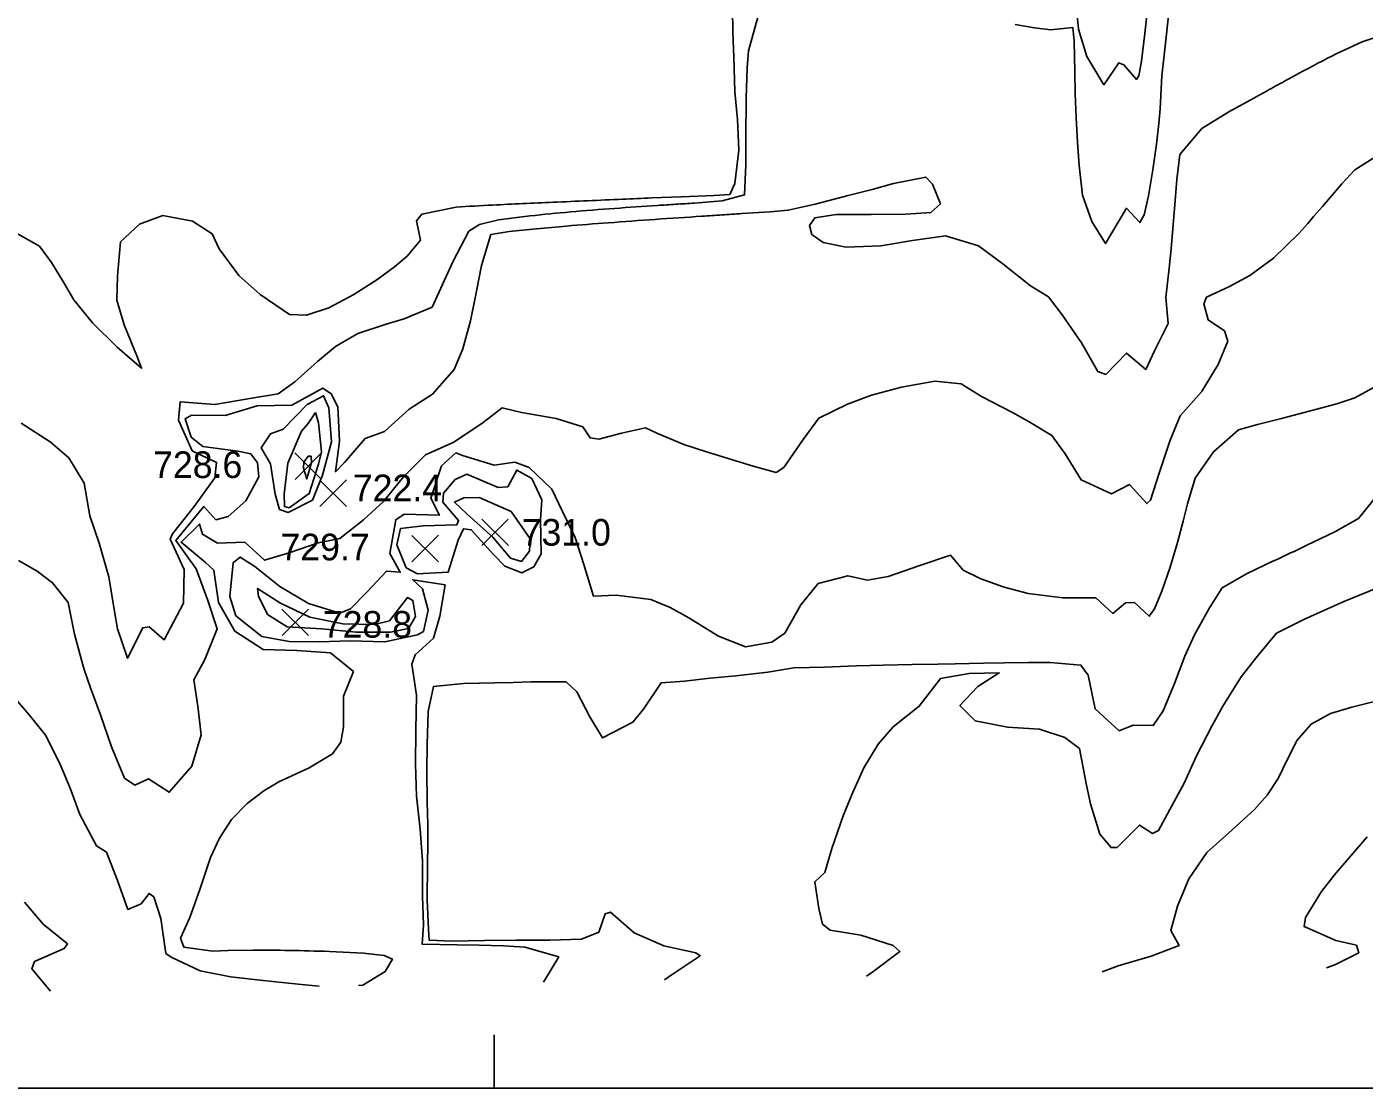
# Model space of a CAD drawing. Extents: x 2566079 to 2571326, y 424054 to 426896.
# Drawn here: x 2568737 to 2569490, y 424077 to 424675 of the extents above; entities that cross this region are included whole.
import ezdxf

# ---------------------------------------------------------------- set-up
doc = ezdxf.new("R2010")
doc.units = 0
for name, color, linetype in [('Contour_ADS_Major', 7, 'Continuous'), ('Contour_ADS_Minor', 7, 'Continuous'), ('Contour_ADS_Spot_Elevation', 7, 'Continuous'), ('Contour_ADS_State_Plane_Border', 7, 'Continuous')]:
    doc.layers.add(name, color=color, linetype=linetype)

# ---------------------------------------------------------------- blocks, each defined once
blk = doc.blocks.new('S750')
at = {"layer": 'Contour_ADS_Spot_Elevation'}
for p, q in [((-0.5, 0.498), (0.5, -0.498)), ((-0.498, -0.5), (0.498, 0.5))]:
    blk.add_line(p, q, dxfattribs=at)

msp = doc.modelspace()

# ---------------------------------------------------------------- linework, layer by layer
at = {"layer": 'Contour_ADS_Major'}
for points in [[(2569148.4, 424680.26), (2569143.26, 424661.28), (2569142.39, 424651.69), (2569141.92, 424634.68)], [(2569379.5, 424681), (2569377.6, 424663.89), (2569375.78, 424647.26), (2569374.83, 424628.73), (2569374.11, 424620.32), (2569372.8, 424608.77), (2569370.8, 424594.24), (2569368.36, 424579.73), (2569365.83, 424568.96), (2569363.52, 424564.6), (2569355.9, 424572.66), (2569347.6, 424558.77), (2569344.15, 424552.78), (2569336.49, 424565.18), (2569331.23, 424580.05), (2569329.37, 424596.73), (2569328.41, 424609.75), (2569327.61, 424623.78), (2569327.12, 424637.23), (2569326.84, 424649.29), (2569326.4, 424666.86), (2569325.64, 424674.5), (2569313.31, 424673.2), (2569304.06, 424674.2), (2569293.31, 424676.06)], [(2569141.74, 424614.53), (2569141.65, 424597.04), (2569140.95, 424580.15), (2569128.29, 424576.79), (2569112.83, 424575.6)], [(2569020.24, 424568.38), (2569002.52, 424566.06), (2568991.77, 424563.55), (2568985.88, 424559.68), (2568976.96, 424542.97), (2568971.94, 424531.73), (2568965.18, 424516.99), (2568949.39, 424510.41), (2568939.36, 424507.46), (2568923.33, 424502.22), (2568910.71, 424494.91), (2568900.61, 424486.41), (2568887.81, 424474.87), (2568878.51, 424468.21), (2568862.59, 424465.54), (2568842.96, 424462.07), (2568823.37, 424463.74), (2568822.37, 424453.26), (2568830.2, 424436.13), (2568843.86, 424429.43), (2568842.85, 424420.84), (2568831.24, 424404.73), (2568819.03, 424389.35), (2568817.81, 424386.3), (2568825.65, 424369.25), (2568825.19, 424350.35), (2568817.96, 424336.48), (2568814.45, 424329.64), (2568805.9, 424336.89), (2568802.3, 424336.46), (2568793.65, 424319.25), (2568788.19, 424335.89), (2568786.44, 424345.58), (2568783.28, 424365.11), (2568777.73, 424384.13), (2568772.56, 424399.48), (2568769.25, 424417.78), (2568760.78, 424432.06), (2568750.24, 424441.21), (2568733.97, 424451.64)], [(2569501.39, 424360.56), (2569487.05, 424354.87), (2569477.9, 424351.07), (2569466.89, 424346.21), (2569455.66, 424341.03), (2569440.33, 424333.31), (2569429.44, 424320.17), (2569420.47, 424308.85), (2569410.19, 424292.35), (2569404, 424280.98), (2569395.34, 424264.39), (2569388.4, 424248.97), (2569380.4, 424234.15), (2569374, 424222.23), (2569370.57, 424220.62), (2569363.2, 424225.3), (2569350.74, 424212.78), (2569347.23, 424212.68), (2569340.83, 424220.23), (2569335.66, 424237.31), (2569333.27, 424248.8), (2569329.46, 424268.4), (2569321.13, 424274.65), (2569306.99, 424279.24), (2569289.01, 424280.5), (2569270.79, 424284.02), (2569262.18, 424292.68), (2569272.27, 424303.38), (2569284.32, 424311.02), (2569267.34, 424310.71), (2569251.23, 424307.8), (2569239.28, 424292.19), (2569224.64, 424280.59), (2569216.08, 424270.97), (2569208.17, 424257.51), (2569201.49, 424242.85), (2569196.53, 424230.47), (2569190.12, 424212.21), (2569186.07, 424198.63), (2569180.58, 424193.37), (2569182.69, 424178.35), (2569184.87, 424169.61), (2569189.07, 424166.21), (2569206.45, 424163.34), (2569224.68, 424157.44), (2569228.45, 424154.08), (2569213.2, 424142.67), (2569209.59, 424140.18)]]:
    msp.add_lwpolyline(points, dxfattribs=at)
msp.add_lwpolyline([(2568984.81, 424400.49), (2568999.4, 424387.44), (2569009.21, 424375.7), (2569015.54, 424373.75), (2569020.04, 424379.57), (2569020.37, 424386.53), (2569009.57, 424401.86), (2568991.66, 424409.74), (2568983.04, 424409.66), (2568977.73, 424407.1), (2568984.81, 424400.49)], close=True, dxfattribs=at)
for centre, radius, start, end in [((2572181.95, 424597.45), 3040.26, 179.29831, 179.67807), ((2569195.24, 422826.96), 1750.28, 94.17446, 94.98989), ((2569403.65, 419848.15), 4736.36, 93.77388, 94.06586), ((2569573.33, 417249.65), 7340.39, 93.678631, 93.76045), ((2569001.81, 426202.51), 1630.69, 273.53539, 273.90369), ((2569128.54, 423575.81), 998.46, 94.91484, 96.22713)]:
    msp.add_arc(centre, radius, start, end, dxfattribs=at)
at = {"layer": 'Contour_ADS_Minor'}
for points in [[(2569134.16, 424685.01), (2569134.46, 424671.9), (2569134.91, 424657.69), (2569135.48, 424638.16), (2569136.95, 424622.74), (2569137.82, 424605.39), (2569135.5, 424586.56), (2569132.71, 424580.47), (2569123.92, 424579.94), (2569105.33, 424579.15), (2569088.82, 424578.45)], [(2569368.25, 424690.31), (2569366.25, 424671.12), (2569364.4, 424655.45), (2569362.9, 424647.22), (2569361.47, 424645.24), (2569354.44, 424653.44), (2569351.53, 424654.49), (2569343.17, 424642.25), (2569333.51, 424658.22), (2569328.88, 424673.45), (2569327.82, 424685.09)], [(2569502.06, 424670.91), (2569488.49, 424666.36)], [(2569427.66, 424634.74), (2569413.53, 424626.97), (2569398.33, 424617.63), (2569385.92, 424602.88), (2569384.26, 424588.83), (2569382.89, 424572.41), (2569382.07, 424561.36), (2569381.09, 424549.85), (2569379.92, 424538.99), (2569377.99, 424522.47), (2569379.32, 424507.7), (2569371.59, 424492.32), (2569366.8, 424481.78), (2569355.83, 424491.11), (2569344.3, 424479.08), (2569339.74, 424480.81), (2569330.51, 424496.86), (2569319.81, 424512.63), (2569311.99, 424522.73), (2569301.96, 424528.99), (2569286.27, 424541.29), (2569272.61, 424551.45), (2569254.01, 424557.05), (2569235.49, 424554.49), (2569217.68, 424551.6), (2569198.25, 424550.8), (2569185.28, 424553.34), (2569178.93, 424557.94), (2569177.46, 424563.01), (2569180.52, 424567.27), (2569192.56, 424569.22), (2569212.21, 424569.25), (2569231.66, 424569.32), (2569245.83, 424570.25), (2569251.18, 424575.18), (2569246.84, 424586.16), (2569242.92, 424590.23), (2569224.88, 424586.64), (2569212.76, 424583.24), (2569199.35, 424579.92), (2569180.63, 424574.93), (2569165.61, 424571.57), (2569155.43, 424570.74), (2569139.52, 424569.66)], [(2569498.08, 424603), (2569484.43, 424594.29), (2569477.09, 424586.48), (2569466.17, 424573.68)], [(2568978.68, 424573.33), (2568959.31, 424569.29), (2568956.42, 424565.64), (2568958.7, 424554.74), (2568951.06, 424545.73), (2568944.05, 424539.74), (2568934.05, 424532.34), (2568921.1, 424524.04), (2568907.1, 424516.69), (2568894.39, 424512.45), (2568884.82, 424512.75), (2568868.44, 424524.2), (2568856.29, 424534.82), (2568845.22, 424549.86), (2568841.35, 424558.2), (2568830.36, 424565.33), (2568813.59, 424568.63), (2568800.43, 424563.8), (2568789.73, 424553.69), (2568788.06, 424534.64), (2568787.72, 424520.95), (2568791.85, 424507.1), (2568799.34, 424488.63), (2568801.68, 424482.57), (2568788, 424494.52), (2568774.08, 424508.1), (2568763.45, 424521.19), (2568757.72, 424531.05), (2568750.96, 424542.19), (2568744.23, 424551.31), (2568729.27, 424559.69)], [(2569040.78, 424562.63), (2569021.91, 424560.97), (2569008.58, 424559.64), (2568998.22, 424557.84), (2568992.9, 424540.38), (2568990.18, 424526.02), (2568986.7, 424509.19), (2568982.46, 424493.54), (2568977.48, 424481.91), (2568965.41, 424467.99), (2568952.17, 424459.56), (2568938.29, 424446.92), (2568927.43, 424442.97), (2568915.87, 424429.41), (2568910.77, 424424.31), (2568912.96, 424441.54), (2568912.08, 424460.87), (2568908.39, 424468.21), (2568903.66, 424471.38), (2568886.16, 424461.73), (2568866.71, 424461.49), (2568848.75, 424455.94), (2568829.82, 424456.2), (2568826.17, 424454.12), (2568829.58, 424443.73), (2568836.05, 424438.58), (2568855.73, 424435.97), (2568863.04, 424434.41), (2568866.88, 424429.3), (2568867.61, 424421.37), (2568860.24, 424407.84), (2568850.3, 424399.04), (2568843.44, 424397.22), (2568836.69, 424404.68), (2568824.36, 424389.76), (2568821.01, 424385.65), (2568832.44, 424369.64), (2568838.93, 424351.8), (2568844.12, 424335.84), (2568837.22, 424318.61), (2568831.1, 424307.1), (2568833.36, 424292.33), (2568835.22, 424276.12), (2568829.95, 424258.55), (2568817.26, 424243.85), (2568805.49, 424251.42), (2568797.79, 424247.72), (2568792.09, 424251.79), (2568784.7, 424269.42), (2568778.5, 424287.31), (2568772.85, 424302.67), (2568769.1, 424313.47), (2568763.91, 424332.77), (2568760.39, 424350.61), (2568751.61, 424361.76), (2568742.83, 424368.33), (2568732.46, 424374.33)], [(2569452.84, 424558.54), (2569438.71, 424544.65), (2569425.31, 424534.79), (2569413.87, 424528.59), (2569400.96, 424522.55), (2569399.39, 424518.92), (2569401.85, 424509.81), (2569411.08, 424503.61), (2569412.89, 424497.87), (2569407.49, 424484.64), (2569398.2, 424469.34), (2569386.14, 424455.71), (2569380.53, 424442.03), (2569374.34, 424423.53), (2569369.44, 424408.21), (2569367.45, 424406.39), (2569357.59, 424417.04), (2569347.4, 424411.88), (2569330.33, 424419.7), (2569321.44, 424434.36), (2569313.9, 424444.71), (2569301.09, 424452.45), (2569291.7, 424457.64), (2569274.36, 424466.71), (2569262.95, 424473.79), (2569248.13, 424475.36), (2569229.25, 424471.86), (2569212.42, 424467.45), (2569198.89, 424462.34), (2569182.69, 424454.38), (2569173.91, 424442.36), (2569163.1, 424426.76), (2569158.78, 424423.92), (2569145.76, 424427.38), (2569133.63, 424431.25), (2569119.59, 424435.51), (2569106.77, 424439.66), (2569091.7, 424446.07), (2569085.18, 424448.93), (2569071.82, 424446), (2569059.05, 424442.64), (2569054.08, 424443.38), (2569049.89, 424449.56), (2569035.05, 424454.24), (2569015.37, 424457.69), (2569004.65, 424460.32), (2568993.93, 424452.08), (2568977.36, 424440.95), (2568961.35, 424433.87), (2568948.97, 424421.39), (2568937.85, 424407.54), (2568926.55, 424397.17), (2568913.28, 424386.74), (2568901.11, 424384.26), (2568884.62, 424378.69), (2568870.84, 424374.49), (2568859.7, 424384.65), (2568844.4, 424384.14), (2568835.97, 424389.06), (2568834.16, 424394.84), (2568823.89, 424384.61), (2568837.66, 424373.1), (2568842.34, 424368.84), (2568845, 424350.64), (2568854.1, 424334.49), (2568870.01, 424324.27), (2568889.09, 424323.54), (2568908.01, 424322.32), (2568920.82, 424311.75), (2568915.35, 424297.91), (2568915.35, 424280.7), (2568913.7, 424272.02), (2568909.05, 424265.39), (2568895.91, 424257.53), (2568878.81, 424249.74), (2568870.41, 424244.54), (2568861.05, 424237.39), (2568852.32, 424228.42), (2568845.47, 424217.98), (2568840.45, 424207.13), (2568834.39, 424189.04), (2568828.78, 424173.21), (2568823.57, 424161.61), (2568825.35, 424156.59), (2568841.83, 424154.38), (2568850.37, 424154.72), (2568864.37, 424154.9)], [(2569496.46, 424472.44), (2569484.39, 424465.86), (2569474.34, 424462.61), (2569459.51, 424458.53), (2569443.18, 424454.3), (2569429.63, 424450.86), (2569419.02, 424447.86), (2569404.86, 424435.47), (2569394.6, 424420.63), (2569390.19, 424406.24), (2569387.8, 424396.49), (2569384.65, 424384.54), (2569380.46, 424370.57), (2569375.87, 424357.09), (2569371.74, 424347.14), (2569368.71, 424342.92), (2569360.48, 424350.75), (2569355.4, 424350.53), (2569348.21, 424344.47), (2569338.63, 424353.28), (2569320.08, 424353.38), (2569300.62, 424355.78), (2569287.17, 424359.37), (2569273.95, 424364.06), (2569264.07, 424368.9), (2569256.81, 424377.26), (2569239.57, 424371.58), (2569221.81, 424365.39), (2569210.26, 424363.24), (2569199.12, 424365.61), (2569182.4, 424361.41), (2569172.69, 424349.41), (2569163.74, 424333.44), (2569156.3, 424328.25), (2569141.45, 424325.71), (2569126.28, 424331.66), (2569109.62, 424342.03), (2569099.13, 424347.84), (2569088.24, 424352.31), (2569068.74, 424354.88), (2569055.95, 424354.27), (2569050.57, 424372.06), (2569045.74, 424387.31), (2569038.45, 424401.97), (2569032.58, 424414.51), (2569019.69, 424426.7), (2569011.7, 424429.68), (2569000.14, 424427.96), (2568982.28, 424433.42), (2568978.59, 424434.86), (2568970.51, 424427.69), (2568964.38, 424409.39), (2568969.3, 424399.84), (2568949.51, 424400.39), (2568944.7, 424397.25), (2568941.34, 424378.23), (2568947.25, 424367.72), (2568939.48, 424368.27), (2568928.57, 424356.63), (2568919.29, 424347.18), (2568913.16, 424344.65), (2568895.61, 424350.13), (2568879.49, 424359.68), (2568865.3, 424371), (2568857.17, 424376.21), (2568853.17, 424373.05), (2568851.38, 424354.13), (2568854.67, 424343.24), (2568869.25, 424331.51), (2568884.74, 424328.74), (2568901.58, 424328.42), (2568919.11, 424329.07), (2568938.5, 424328.51), (2568956.9, 424332.44), (2568960.33, 424334.42), (2568962.92, 424346.34), (2568959.71, 424358.29), (2568954.28, 424363.45), (2568972.49, 424360.52), (2568969.55, 424342.95), (2568965.94, 424330.62), (2568955.66, 424321.2), (2568953.69, 424315.9), (2568956.33, 424298.47), (2568956.03, 424278.82), (2568955.86, 424259.55), (2568956.41, 424241.57), (2568958.34, 424223.02), (2568959.67, 424205.27)], [(2569617.85, 424456.24), (2569605.01, 424453.48), (2569586.25, 424449.5), (2569571.48, 424444.86), (2569559.82, 424438.14), (2569543.01, 424430.38), (2569528.5, 424428), (2569516.06, 424422.36), (2569502.02, 424411.97), (2569496.79, 424410.64), (2569486.43, 424397.99), (2569473.22, 424390.53), (2569457.46, 424382.89)], [(2569439.09, 424374.22), (2569423.38, 424366.83), (2569409.68, 424358.97), (2569402.6, 424347.59), (2569394.15, 424332.38), (2569388.74, 424320.35), (2569382.92, 424304.98), (2569376.53, 424289.59), (2569370.95, 424281.32), (2569359.62, 424281.67), (2569351.78, 424278.48), (2569338.23, 424290.72), (2569334.42, 424309.76), (2569330.26, 424315.43), (2569312.94, 424316.92), (2569300.78, 424316.83), (2569287.28, 424316.63), (2569275.37, 424316.42), (2569259.47, 424316.13), (2569249.72, 424315.98), (2569235.39, 424315.74), (2569218.92, 424315.43), (2569203.92, 424315.04), (2569186.06, 424314.23), (2569168.69, 424313.92), (2569154.07, 424311.36), (2569136.08, 424309.34), (2569121.62, 424308.11), (2569107.13, 424306.42), (2569093.96, 424305.39), (2569084.02, 424290.64), (2569078.13, 424283.21), (2569061.09, 424274.45), (2569053.98, 424286.36), (2569046.59, 424300.3), (2569040.55, 424305.9), (2569020.67, 424306.01), (2569010.79, 424305.7), (2569000.44, 424305.47), (2568982.72, 424305.06), (2568965.85, 424303.35), (2568963.02, 424289.33), (2568962.46, 424270.76), (2568962.22, 424255.78), (2568962.35, 424238.34), (2568962.71, 424225.6), (2568962.7, 424214.78), (2568962.58, 424202.86), (2568962.36, 424183.34), (2568963.15, 424166.47), (2568963.58, 424160.46), (2568976.26, 424159.87), (2568994.62, 424160.37), (2569012.58, 424160.51), (2569031.39, 424160.59), (2569049.16, 424160.99), (2569058.99, 424165.08), (2569062.51, 424175.36), (2569065.63, 424176.33), (2569078.85, 424164.64), (2569095.46, 424157.3), (2569113.65, 424153.34), (2569116.02, 424151.69), (2569099.77, 424140.72), (2569095.95, 424138.11)], [(2568901.64, 424134.58), (2568891.69, 424135.54), (2568880.74, 424136.69), (2568870.01, 424137.81), (2568851.76, 424139.79), (2568834.63, 424143.15), (2568818.3, 424150.9), (2568815.25, 424153.09), (2568812.47, 424172.72), (2568808.52, 424184.85), (2568805.83, 424186.86), (2568801.39, 424181), (2568793.98, 424177.82), (2568788.12, 424194.12), (2568781.86, 424210.1), (2568776.2, 424213.58), (2568766.96, 424231.28), (2568761.38, 424246.15), (2568756.07, 424259.03), (2568747.83, 424275.82), (2568738.35, 424287.36), (2568728.28, 424299.26)], [(2569500.77, 424296.26), (2569482.67, 424291.78), (2569470.73, 424288.17), (2569459.78, 424282.08), (2569452.03, 424273.06), (2569446.47, 424262.36), (2569441.29, 424251.63), (2569435.06, 424242.2), (2569427.95, 424234.11), (2569413.34, 424220.75), (2569401.22, 424209.8), (2569390.91, 424195.07), (2569384.61, 424179.69), (2569380.93, 424166.02), (2569385.49, 424157.42), (2569369.84, 424151.57), (2569351.29, 424145.98), (2569342.27, 424142.59)], [(2569491.35, 424218.61), (2569482.09, 424208.09), (2569473.06, 424197.34), (2569465.65, 424187.97), (2569456.73, 424173.27), (2569455.83, 424168.12), (2569473.82, 424160.4), (2569485.31, 424157.67), (2569486.58, 424153.41), (2569473.15, 424146.57), (2569468.42, 424144.89)], [(2568959.67, 424205.27), (2568959.83, 424185.38), (2568960.29, 424169.07), (2568959.63, 424158.19), (2568979.18, 424157.84), (2568991.63, 424157.76), (2569005.24, 424157.4), (2569017.32, 424156.59), (2569036.37, 424151.07), (2569027.83, 424136.87)], [(2568750.48, 424131.83), (2568739.9, 424144.29), (2568741.33, 424148.43), (2568758.09, 424155.79), (2568760.03, 424158.36), (2568746.2, 424169.44), (2568735.8, 424182)], [(2568907.32, 424154.13), (2568926.55, 424153.19), (2568938.16, 424151.87), (2568942.82, 424149.89), (2568938.79, 424142.82), (2568926.09, 424135.23), (2568923.64, 424134.98)]]:
    msp.add_lwpolyline(points, dxfattribs=at)
for points in [[(2568894.82, 424462.23), (2568881.39, 424448.26), (2568874.13, 424445.59), (2568869.02, 424437.71), (2568874.17, 424428.69), (2568876.89, 424411.73), (2568879.23, 424403.11), (2568884.21, 424401.28), (2568897.82, 424408.23), (2568903.53, 424422.32), (2568908.48, 424441.16), (2568907.09, 424460.37), (2568904.06, 424467.1), (2568894.82, 424462.23)], [(2568899.45, 424457.58), (2568895.48, 424451.44), (2568891.67, 424447.17), (2568883.94, 424429.15), (2568881.8, 424411.64), (2568882.03, 424404.72), (2568884.77, 424403.9), (2568895.9, 424412.04), (2568901.18, 424428.55), (2568902.95, 424435.5), (2568901.12, 424451.87), (2568899.45, 424457.58)], [(2568892.8, 424426.38), (2568894.64, 424420.27), (2568897.36, 424429.59), (2568897.05, 424433.05), (2568895.47, 424433.12), (2568892.87, 424429.6), (2568892.8, 424426.38)], [(2568950.49, 424370.23), (2568956.98, 424366.83), (2568974.27, 424367.74), (2568979.78, 424385.83), (2568982.77, 424392.22), (2568987.22, 424391.63), (2568999.95, 424377.54), (2569006.08, 424371.11), (2569015.67, 424367.44), (2569022.34, 424370.8), (2569026.58, 424378.06), (2569026.15, 424397.42), (2569026.82, 424408.43), (2569021.25, 424420.4), (2569012.82, 424425.19), (2569007.76, 424415.82), (2569002.36, 424415.48), (2568984.64, 424422.96), (2568978.09, 424419.97), (2568971.56, 424412.17), (2568971.24, 424407.16), (2568980.04, 424396.89), (2568978.99, 424394.44), (2568960.16, 424393.8), (2568947.43, 424392.29), (2568945.35, 424383.17), (2568950.49, 424370.23)], [(2568867.37, 424354.22), (2568872.56, 424343.91), (2568883.56, 424336.96), (2568903.09, 424335.82), (2568922.37, 424333.93), (2568941.73, 424333.89), (2568951.81, 424336.07), (2568955.88, 424342.82), (2568954.33, 424351.87), (2568951.24, 424353.4), (2568941.11, 424340.36), (2568932.77, 424338.26), (2568915, 424338.7), (2568896.38, 424342.42), (2568879.87, 424350.26), (2568866.92, 424358.59), (2568867.37, 424354.22)]]:
    msp.add_lwpolyline(points, close=True, dxfattribs=at)
for centre, radius, start, end in [((2569618.34, 424367.34), 325.99, 113.47287, 117.24488), ((2569934.04, 423756.85), 1013.28, 117.31245, 118.70678), ((2562471.04, 437240.02), 14397.49, 298.893503, 298.938194), ((2570177.62, 423308.1), 1523.87, 118.63535, 119.05774), ((2570469.45, 391820.16), 32787.37, 92.413364, 92.442242), ((2569071.7, 423097.24), 1479.02, 92.80957, 93.60575), ((2569356.15, 417253.85), 7329.33, 92.525156, 92.791467), ((2570015.18, 402321.78), 22275.93, 92.425886, 92.526497), ((2568932.45, 425030.16), 702.31, 317.81486, 319.46059), ((2569283.72, 421652.08), 2920.67, 94.31042, 94.7713), ((2569421.96, 419787.32), 4790.55, 93.96522, 94.28287), ((2569767.04, 414757.31), 9832.38, 93.790619, 93.9444), ((2570007.81, 411111.61), 13486.02, 93.739417, 93.787317), ((2568363.06, 436288.04), 11744.08, 273.735867, 273.790869), ((2568675.21, 426031.22), 1824.53, 295.06863, 295.38765), ((2564098.85, 435681.81), 12505.19, 295.279969, 295.326494), ((2568864.89, 423116.01), 1038.89, 88.90382, 90.02841), ((2568867.49, 423043.99), 1110.85, 87.94529, 89.1093)]:
    msp.add_arc(centre, radius, start, end, dxfattribs=at)
at = {"layer": 'Contour_ADS_State_Plane_Border'}
msp.add_line((2569000, 424077.11), (2569000, 424107.11), dxfattribs=at)
msp.add_lwpolyline([(2566079.33, 424077.11), (2571302.93, 424077.11), (2571302.93, 426873.74), (2566079.33, 426873.74), (2566079.33, 424077.11)], close=True, dxfattribs=at)

# ---------------------------------------------------------------- block references
at = {"layer": 'Contour_ADS_Spot_Elevation', "xscale": 15, "yscale": 15}
for p in [(2568895.47, 424427.4), (2568909.45, 424412.17), (2569000.57, 424390.17), (2568961.27, 424380.99), (2568888.16, 424339.5)]:
    msp.add_blockref('S750', p, dxfattribs=at)

# ---------------------------------------------------------------- texts
at = {"layer": 'Contour_ADS_Spot_Elevation'}
for s, p in [('728.6', (2568808.13, 424420.76)), ('722.4', (2568920.55, 424407.7)), ('731.0', (2569015.57, 424382.67)), ('729.7', (2568879.82, 424374.41)), ('728.8', (2568903.67, 424330.86))]:
    msp.add_text(s, height=15, dxfattribs=at).set_placement(p)

doc.saveas('drawing.dxf')
